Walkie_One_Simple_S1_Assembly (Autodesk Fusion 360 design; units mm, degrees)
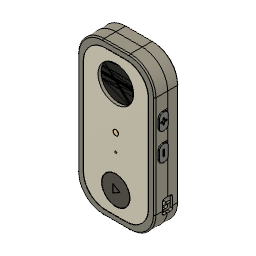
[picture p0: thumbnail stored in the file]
part number: 2026-09-16-19-14-38-361
part number: 2026-09-16-19-14-38-919
part number: 2026-09-16-19-14-39-016
part number: 2026-09-16-19-14-39-115
part number: 2026-09-16-19-14-39-169
part number: 2026-09-16-19-14-39-241
part number: 2026-09-16-19-14-39-296
part number: 2026-09-16-19-14-39-373
part number: 2026-09-16-19-14-39-442
part number: 2026-09-16-19-14-39-821
part number: 2026-09-16-19-14-39-875
part number: 2026-09-16-19-14-39-946
part number: 2026-09-16-19-14-39-999
part number: 2026-09-16-19-14-40-066
part number: 2026-09-16-19-14-40-133
part number: 2026-09-16-19-14-40-204
part number: 2026-09-16-19-14-40-267
part number: 2026-09-16-19-14-40-342
part number: 2026-09-16-19-06-38-531_1
part number: 2026-09-16-19-06-38-530_4
parameter "Overall_width_limit" = 78 comment "S1 design datum; rebuild source uses these stated values"
parameter "Case_width" = 76 comment "S1 design datum; rebuild source uses these stated values"
parameter "Case_height" = 150 comment "S1 design datum; rebuild source uses these stated values"
parameter "Case_depth" = 24 comment "S1 design datum; rebuild source uses these stated values"
parameter "Wall" = 2.4 comment "S1 design datum; rebuild source uses these stated values"
parameter "Front_skin" = 3 comment "S1 design datum; rebuild source uses these stated values"
parameter "Plan_corner" = 25 comment "S1 design datum; rebuild source uses these stated values"
parameter "Button_clearance_each_side" = 0.35 comment "S1 design datum; rebuild source uses these stated values"
base_feature "Base Feature1" bodies "03_Talk"
base_feature "Base Feature1" bodies "04_Volume_Up"
base_feature "Base Feature1" bodies "05_Volume_Down"
place_component sketch "Play symbol"
base_feature "Base Feature1" sketch "Play symbol" bodies "06_Play"
place_component sketch "45 degree reflector"
base_feature "Base Feature1" sketch "45 degree reflector" bodies "07_Control_Bridge"
base_feature "Base Feature1" bodies "08_Light_Guide_CLEAR"
base_feature "Base Feature1" bodies "01_Front_Shell"
base_feature "Base Feature1" bodies "02_Rear_Cover"
fillet "Fillet1" radius 1.2
fillet "Fillet1" radius 1.2
sketch "Play symbol" plane through (0, 0, 0) normal (0, 0, 1) x axis (1, 0, 0)
  line L1 (4, -47) -> (-3, -51)
  line L2 (-3, -43) -> (4, -47)
  line L3 (-3, -51) -> (-3, -43)
extrude "Extrude1" cut sketch "Play symbol" against normal blind 0.35 (magnitude of "-( 0.35 mm )")
work_plane "WorkPlane1" AlongDistance -2 ExtraOffset 0
sketch "45 degree reflector" plane through (0, -2, 0) normal (0, 1, 0) x axis (1, 0, 0)
  line L1 (3, 10) -> (-3, 10)
  line L2 (3, 4) -> (3, 10)
  line L3 (-3, 10) -> (3, 4)
extrude "Extrude1" cut sketch "45 degree reflector" distance 12
base_feature "Base Feature1" bodies "REF_03_Talk_switch_NOMINAL"
base_feature "Base Feature1" bodies "REF_04_Volume_Up_switch_NOMINAL"
base_feature "Base Feature1" bodies "REF_05_Volume_Down_switch_NOMINAL"
base_feature "Base Feature1" bodies "REF_Play_switch_12x12x4p3_NOMINAL"
base_feature "Base Feature1" bodies "REF_Battery_MAX_62x38p5x8p5"
base_feature "Base Feature1" bodies "REF_Antenna_96x21x0p2"
base_feature "Base Feature1" bodies "CHECK_J2_PHR_and_wire_turn"
base_feature "Base Feature1" bodies "CHECK_J10_PHR_and_wire_turn"
base_feature "Base Feature1" bodies "CHECK_J3_PHR_and_wire_turn"
base_feature "Base Feature1"
base_feature "Base Feature1"
base_feature "Base Feature1"
base_feature "Base Feature1"
base_feature "Base Feature1"
base_feature "Base Feature1"
base_feature "Base Feature1"
base_feature "Base Feature1"
base_feature "Base Feature1"
base_feature "Base Feature1"
base_feature "Base Feature1"
base_feature "Base Feature1"
base_feature "Base Feature1"
base_feature "Base Feature1"
base_feature "Base Feature1"
base_feature "Base Feature1"
base_feature "Base Feature1"
base_feature "Base Feature1"
base_feature "Base Feature1"
base_feature "Base Feature1"
base_feature "Base Feature1"
base_feature "Base Feature1"
base_feature "Base Feature1"
base_feature "Base Feature1"
base_feature "Base Feature1"
base_feature "Base Feature1"
base_feature "Base Feature1"
base_feature "Base Feature1"
base_feature "Base Feature1"
base_feature "Base Feature1"
base_feature "Base Feature1"
base_feature "Base Feature1"
base_feature "Base Feature1"
base_feature "Base Feature1"
base_feature "Base Feature1"
base_feature "Base Feature1"
base_feature "Base Feature1"
base_feature "Base Feature1"
base_feature "Base Feature1"
base_feature "Base Feature1"
base_feature "Base Feature1"
base_feature "Base Feature1"
base_feature "Base Feature1"
base_feature "Base Feature1"
base_feature "Base Feature1"
base_feature "Base Feature1"
base_feature "Base Feature1"
base_feature "Base Feature1"
base_feature "Base Feature1"
base_feature "Base Feature1"
base_feature "Base Feature1"
base_feature "Base Feature1"
base_feature "Base Feature1"
base_feature "Base Feature1"
base_feature "Base Feature1"
base_feature "Base Feature1"
base_feature "Base Feature1"
base_feature "Base Feature1"
base_feature "Base Feature1"
base_feature "Base Feature1"
base_feature "Base Feature1"
base_feature "Base Feature1"
base_feature "Base Feature1"
base_feature "Base Feature1"
base_feature "Base Feature1"
base_feature "Base Feature1"
base_feature "Base Feature1"
base_feature "Base Feature1"
base_feature "Base Feature1"
base_feature "Base Feature1"
base_feature "Base Feature1"
base_feature "Base Feature1"
base_feature "Base Feature1"
base_feature "Base Feature1"
base_feature "Base Feature1"
base_feature "Base Feature1"
base_feature "Base Feature1"
base_feature "Base Feature1"
base_feature "Base Feature1"
base_feature "Base Feature1"
base_feature "Base Feature1"
base_feature "Base Feature1"
base_feature "Base Feature1"
base_feature "Base Feature1"
base_feature "Base Feature1"
base_feature "Base Feature1"
base_feature "Base Feature1"
base_feature "Base Feature1"
base_feature "Base Feature1"
base_feature "Base Feature1"
base_feature "Base Feature1"
base_feature "Base Feature1"
base_feature "Base Feature1"
base_feature "Base Feature1"
base_feature "Base Feature1"
base_feature "Base Feature1"
base_feature "Base Feature1"
base_feature "Base Feature1"
base_feature "Base Feature1"
base_feature "Base Feature1"
base_feature "Base Feature1"
base_feature "Base Feature1"
base_feature "Base Feature1"
base_feature "Base Feature1"
base_feature "Base Feature1"
base_feature "Base Feature1"
base_feature "Base Feature1"
base_feature "Base Feature1"
base_feature "Base Feature1"
base_feature "Base Feature1"
base_feature "Base Feature1"
base_feature "Base Feature1"
base_feature "Base Feature1"
base_feature "Base Feature1"
base_feature "Base Feature1"
base_feature "Base Feature1"
base_feature "Base Feature1"
base_feature "Base Feature1"
base_feature "Base Feature1"
base_feature "Base Feature1"
base_feature "Base Feature1"
base_feature "Base Feature1"
base_feature "Base Feature1"
base_feature "Base Feature1"
base_feature "Base Feature1"
base_feature "Base Feature1"
base_feature "Base Feature1"
base_feature "Base Feature1"
base_feature "Base Feature1"
base_feature "Base Feature1"
base_feature "Base Feature1"
base_feature "Base Feature1"
base_feature "Base Feature1"
base_feature "Base Feature1"
base_feature "Base Feature1"
base_feature "Base Feature1"
base_feature "Base Feature1"
base_feature "Base Feature1"
base_feature "Base Feature1"
base_feature "Base Feature1"
base_feature "Base Feature1"
base_feature "Base Feature1"
base_feature "Base Feature1"
base_feature "Base Feature1"
base_feature "Base Feature1"
base_feature "Base Feature1"
base_feature "Base Feature1"
base_feature "Base Feature1"
base_feature "Base Feature1"
base_feature "Base Feature1"
base_feature "Base Feature1"
base_feature "Base Feature1"
base_feature "Base Feature1"
base_feature "Base Feature1"
base_feature "Base Feature1"
base_feature "Base Feature1"
base_feature "Base Feature1"
base_feature "Base Feature1"
base_feature "Base Feature1"
base_feature "Base Feature1"
base_feature "Base Feature1"
base_feature "Base Feature1"
base_feature "Base Feature1"
base_feature "Base Feature1"
base_feature "Base Feature1"
base_feature "Base Feature1"
base_feature "Base Feature1"
base_feature "Base Feature1"
base_feature "Base Feature1"
base_feature "Base Feature1"
base_feature "Base Feature1"
base_feature "Base Feature1"
base_feature "Base Feature1"
base_feature "Base Feature1"
base_feature "Base Feature1"
base_feature "Base Feature1"
base_feature "Base Feature1"
base_feature "Base Feature1"
base_feature "Base Feature1"
base_feature "Base Feature1"
base_feature "Base Feature1"
base_feature "Base Feature1"
base_feature "Base Feature1"
base_feature "Base Feature1"
base_feature "Base Feature1"
base_feature "Base Feature1"
base_feature "Base Feature1"
base_feature "Base Feature1"
base_feature "Base Feature1"
base_feature "Base Feature1"
base_feature "Base Feature1"
base_feature "Base Feature1"
base_feature "Base Feature1"
base_feature "Base Feature1"
base_feature "Base Feature1"
base_feature "Base Feature1"
base_feature "Base Feature1"
base_feature "Base Feature1"
base_feature "Base Feature1"
base_feature "Base Feature1"
base_feature "Base Feature1"
base_feature "Base Feature1"
base_feature "Base Feature1"
base_feature "Base Feature1"
base_feature "Base Feature1"
base_feature "Base Feature1"
base_feature "Base Feature1"
base_feature "Base Feature1"
base_feature "Base Feature1"
base_feature "Base Feature1"
base_feature "Base Feature1"
base_feature "Base Feature1"
base_feature "Base Feature1"
base_feature "Base Feature1"
base_feature "Base Feature1"
base_feature "Base Feature1"
base_feature "Base Feature1"
base_feature "Base Feature1"
base_feature "Base Feature1"
base_feature "Base Feature1"
base_feature "Base Feature1"
base_feature "Base Feature1"
base_feature "Base Feature1"
base_feature "Base Feature1"
base_feature "Base Feature1"
base_feature "Base Feature1"
base_feature "Base Feature1"
base_feature "Base Feature1"
base_feature "Base Feature1"
base_feature "Base Feature1"
base_feature "Base Feature1"
base_feature "Base Feature1"
base_feature "Base Feature1"
base_feature "Base Feature1"
base_feature "Base Feature1"
base_feature "Base Feature1"
base_feature "Base Feature1"
base_feature "Base Feature1"
base_feature "Base Feature1"
base_feature "Base Feature1"
base_feature "Base Feature1"
base_feature "Base Feature1"
base_feature "Base Feature1"
base_feature "Base Feature1"
base_feature "Base Feature1"
base_feature "Base Feature1"
base_feature "Base Feature1"
base_feature "Base Feature1"
base_feature "Base Feature1"
base_feature "Base Feature1"
base_feature "Base Feature1"
base_feature "Base Feature1"
base_feature "Base Feature1"
base_feature "Base Feature1"
base_feature "Base Feature1"
base_feature "Base Feature1"
base_feature "Base Feature1"
base_feature "Base Feature1"
base_feature "Base Feature1"
base_feature "Base Feature1"
base_feature "Base Feature1"
base_feature "Base Feature1"
base_feature "Base Feature1"
base_feature "Base Feature1"
base_feature "Base Feature1"
base_feature "Base Feature1"
base_feature "Base Feature1"
base_feature "Base Feature1"
base_feature "Base Feature1"
base_feature "Base Feature1"
base_feature "Base Feature1"
base_feature "Base Feature1"
base_feature "Base Feature1"
base_feature "Base Feature1"
base_feature "Base Feature1"
base_feature "Base Feature1"
base_feature "Base Feature1"
base_feature "Base Feature1"
base_feature "Base Feature1"
base_feature "Base Feature1"
base_feature "Base Feature1"
base_feature "Base Feature1"
base_feature "Base Feature1"
base_feature "Base Feature1"
base_feature "Base Feature1"
base_feature "Base Feature1"
base_feature "Base Feature1"
base_feature "Base Feature1"
base_feature "Base Feature1"
base_feature "Base Feature1"
base_feature "Base Feature1"
base_feature "Base Feature1"
base_feature "Base Feature1"
base_feature "Base Feature1"
base_feature "Base Feature1"
base_feature "Base Feature1"
base_feature "Base Feature1"
base_feature "Base Feature1"
base_feature "Base Feature1"
base_feature "Base Feature1"
base_feature "Base Feature1"
base_feature "Base Feature1"
base_feature "Base Feature1"
base_feature "Base Feature1"
base_feature "Base Feature1"
base_feature "Base Feature1"
base_feature "Base Feature1"
base_feature "Base Feature1"
base_feature "Base Feature1"
base_feature "Base Feature1"
base_feature "Base Feature1"
base_feature "Base Feature1"
base_feature "Base Feature1"
base_feature "Base Feature1"
base_feature "Base Feature1"
base_feature "Base Feature1"
base_feature "Base Feature1"
base_feature "Base Feature1"
base_feature "Base Feature1"
base_feature "Base Feature1"
base_feature "Base Feature1"
base_feature "Base Feature1"
base_feature "Base Feature1"
base_feature "Base Feature1"
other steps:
extrude "Extrude1" cut sketch "45 degree reflector" distance 12
create_component "CreateComponent1"
create_component "CreateComponent2"
create_component "CreateComponent3"
create_component "CreateComponent4" sketch "Play symbol"
create_component "CreateComponent5" sketch "45 degree reflector"
create_component "CreateComponent6"
create_component "CreateComponent7"
create_component "CreateComponent8"
create_component "CreateComponent9"
create_component "CreateComponent10"
create_component "CreateComponent11"
create_component "CreateComponent12"
create_component "CreateComponent13"
create_component "CreateComponent14"
create_component "CreateComponent15"
create_component "CreateComponent16"
create_component "CreateComponent17"
create_component "CreateComponent18"
create_component "CreateComponent1"
create_component "CreateComponent2"
create_component "CreateComponent3"
create_component "CreateComponent4"
create_component "CreateComponent5"
create_component "CreateComponent6"
create_component "CreateComponent7"
create_component "CreateComponent8"
create_component "CreateComponent9"
create_component "CreateComponent10"
create_component "CreateComponent11"
create_component "CreateComponent12"
create_component "CreateComponent13"
create_component "CreateComponent14"
create_component "CreateComponent15"
create_component "CreateComponent16"
create_component "CreateComponent17"
create_component "CreateComponent18"
create_component "CreateComponent19"
create_component "CreateComponent20"
create_component "CreateComponent21"
create_component "CreateComponent22"
create_component "CreateComponent23"
create_component "CreateComponent24"
create_component "CreateComponent25"
create_component "CreateComponent26"
create_component "CreateComponent27"
create_component "CreateComponent28"
create_component "CreateComponent29"
create_component "CreateComponent30"
create_component "CreateComponent31"
create_component "CreateComponent32"
create_component "CreateComponent33"
create_component "CreateComponent34"
create_component "CreateComponent35"
create_component "CreateComponent36"
create_component "CreateComponent37"
create_component "CreateComponent38"
create_component "CreateComponent39"
create_component "CreateComponent40"
create_component "CreateComponent41"
create_component "CreateComponent42"
create_component "CreateComponent43"
create_component "CreateComponent44"
create_component "CreateComponent45"
create_component "CreateComponent46"
create_component "CreateComponent47"
create_component "CreateComponent48"
create_component "CreateComponent49"
create_component "CreateComponent50"
create_component "CreateComponent51"
create_component "CreateComponent52"
create_component "CreateComponent53"
create_component "CreateComponent54"
create_component "CreateComponent55"
create_component "CreateComponent56"
create_component "CreateComponent57"
create_component "CreateComponent58"
create_component "CreateComponent59"
create_component "CreateComponent60"
create_component "CreateComponent61"
create_component "CreateComponent62"
create_component "CreateComponent63"
create_component "CreateComponent64"
create_component "CreateComponent65"
create_component "CreateComponent66"
create_component "CreateComponent67"
create_component "CreateComponent68"
create_component "CreateComponent69"
create_component "CreateComponent70"
create_component "CreateComponent71"
create_component "CreateComponent72"
create_component "CreateComponent73"
create_component "CreateComponent74"
create_component "CreateComponent75"
create_component "CreateComponent76"
create_component "CreateComponent77"
create_component "CreateComponent78"
create_component "CreateComponent79"
create_component "CreateComponent80"
create_component "CreateComponent81"
create_component "CreateComponent82"
create_component "CreateComponent83"
create_component "CreateComponent84"
create_component "CreateComponent85"
create_component "CreateComponent86"
create_component "CreateComponent87"
create_component "CreateComponent88"
create_component "CreateComponent89"
create_component "CreateComponent90"
create_component "CreateComponent91"
create_component "CreateComponent92"
create_component "CreateComponent93"
create_component "CreateComponent94"
create_component "CreateComponent95"
create_component "CreateComponent96"
create_component "CreateComponent97"
create_component "CreateComponent98"
create_component "CreateComponent99"
create_component "CreateComponent100"
create_component "CreateComponent101"
create_component "CreateComponent102"
create_component "CreateComponent103"
create_component "CreateComponent104"
create_component "CreateComponent105"
create_component "CreateComponent106"
create_component "CreateComponent107"
create_component "CreateComponent108"
create_component "CreateComponent109"
create_component "CreateComponent110"
create_component "CreateComponent111"
create_component "CreateComponent112"
create_component "CreateComponent113"
create_component "CreateComponent114"
create_component "CreateComponent115"
create_component "CreateComponent116"
create_component "CreateComponent117"
create_component "CreateComponent118"
create_component "CreateComponent119"
create_component "CreateComponent120"
create_component "CreateComponent121"
create_component "CreateComponent122"
create_component "CreateComponent123"
create_component "CreateComponent124"
create_component "CreateComponent125"
create_component "CreateComponent126"
create_component "CreateComponent127"
create_component "CreateComponent128"
create_component "CreateComponent129"
create_component "CreateComponent130"
create_component "CreateComponent131"
create_component "CreateComponent132"
create_component "CreateComponent133"
create_component "CreateComponent134"
create_component "CreateComponent135"
create_component "CreateComponent136"
create_component "CreateComponent137"
create_component "CreateComponent138"
create_component "CreateComponent139"
create_component "CreateComponent140"
create_component "CreateComponent141"
create_component "CreateComponent142"
create_component "CreateComponent143"
create_component "CreateComponent144"
create_component "CreateComponent145"
create_component "CreateComponent146"
create_component "CreateComponent147"
create_component "CreateComponent148"
create_component "CreateComponent149"
create_component "CreateComponent150"
create_component "CreateComponent151"
create_component "CreateComponent152"
create_component "CreateComponent153"
create_component "CreateComponent154"
create_component "CreateComponent155"
create_component "CreateComponent156"
create_component "CreateComponent157"
create_component "CreateComponent158"
create_component "CreateComponent159"
create_component "CreateComponent160"
create_component "CreateComponent161"
create_component "CreateComponent162"
create_component "CreateComponent163"
create_component "CreateComponent164"
create_component "CreateComponent165"
create_component "CreateComponent166"
create_component "CreateComponent167"
create_component "CreateComponent168"
create_component "CreateComponent169"
create_component "CreateComponent170"
create_component "CreateComponent171"
create_component "CreateComponent172"
create_component "CreateComponent173"
create_component "CreateComponent174"
create_component "CreateComponent175"
create_component "CreateComponent176"
create_component "CreateComponent177"
create_component "CreateComponent178"
create_component "CreateComponent179"
create_component "CreateComponent180"
create_component "CreateComponent181"
create_component "CreateComponent182"
create_component "CreateComponent183"
create_component "CreateComponent184"
create_component "CreateComponent185"
create_component "CreateComponent186"
create_component "CreateComponent187"
create_component "CreateComponent188"
create_component "CreateComponent189"
create_component "CreateComponent190"
create_component "CreateComponent191"
create_component "CreateComponent192"
create_component "CreateComponent193"
create_component "CreateComponent194"
create_component "CreateComponent195"
create_component "CreateComponent196"
create_component "CreateComponent197"
create_component "CreateComponent198"
create_component "CreateComponent199"
create_component "CreateComponent200"
create_component "CreateComponent201"
create_component "CreateComponent202"
create_component "CreateComponent203"
create_component "CreateComponent204"
create_component "CreateComponent205"
create_component "CreateComponent206"
create_component "CreateComponent207"
create_component "CreateComponent208"
create_component "CreateComponent209"
create_component "CreateComponent210"
create_component "CreateComponent211"
create_component "CreateComponent212"
create_component "CreateComponent213"
create_component "CreateComponent214"
create_component "CreateComponent215"
create_component "CreateComponent216"
create_component "CreateComponent217"
create_component "CreateComponent218"
create_component "CreateComponent219"
create_component "CreateComponent220"
create_component "CreateComponent221"
create_component "CreateComponent222"
create_component "CreateComponent223"
create_component "CreateComponent224"
create_component "CreateComponent225"
create_component "CreateComponent226"
create_component "CreateComponent227"
create_component "CreateComponent228"
create_component "CreateComponent229"
create_component "CreateComponent230"
create_component "CreateComponent231"
create_component "CreateComponent232"
create_component "CreateComponent233"
create_component "CreateComponent234"
create_component "CreateComponent235"
create_component "CreateComponent236"
create_component "CreateComponent237"
create_component "CreateComponent238"
create_component "CreateComponent239"
create_component "CreateComponent240"
create_component "CreateComponent241"
create_component "CreateComponent242"
create_component "CreateComponent243"
create_component "CreateComponent244"
create_component "CreateComponent245"
create_component "CreateComponent246"
create_component "CreateComponent247"
create_component "CreateComponent248"
create_component "CreateComponent249"
create_component "CreateComponent250"
create_component "CreateComponent251"
create_component "CreateComponent252"
create_component "CreateComponent253"
create_component "CreateComponent254"
create_component "CreateComponent255"
create_component "CreateComponent256"
create_component "CreateComponent257"
create_component "CreateComponent258"
create_component "CreateComponent259"
create_component "CreateComponent260"
create_component "CreateComponent261"
create_component "CreateComponent262"
create_component "CreateComponent263"
create_component "CreateComponent264"
create_component "CreateComponent265"
create_component "CreateComponent266"
create_component "CreateComponent267"
create_component "CreateComponent268"
create_component "CreateComponent269"
create_component "CreateComponent270"
create_component "CreateComponent271"
create_component "CreateComponent272"
create_component "CreateComponent273"
create_component "CreateComponent274"
create_component "CreateComponent275"
create_component "CreateComponent276"
create_component "CreateComponent277"
create_component "CreateComponent278"
create_component "CreateComponent279"
create_component "CreateComponent280"
create_component "CreateComponent281"
create_component "CreateComponent282"
create_component "CreateComponent283"
create_component "CreateComponent284"
create_component "CreateComponent285"
create_component "CreateComponent286"
create_component "CreateComponent287"
create_component "CreateComponent288"
create_component "CreateComponent289"
create_component "CreateComponent290"
create_component "CreateComponent291"
create_component "CreateComponent292"
create_component "CreateComponent293"
create_component "CreateComponent294"
create_component "CreateComponent295"
create_component "CreateComponent296"
create_component "CreateComponent297"
create_component "CreateComponent298"
create_component "CreateComponent299"
create_component "CreateComponent300"
create_component "CreateComponent301"
create_component "CreateComponent302"
create_component "CreateComponent303"
create_component "CreateComponent304"
create_component "CreateComponent305"
create_component "CreateComponent306"
create_component "CreateComponent19"
create_component "CreateComponent20"
create_component "CreateComponent1"
create_component "CreateComponent2"
create_component "CreateComponent3"
create_component "CreateComponent4"
create_component "CreateComponent21"
create_component "CreateComponent1"
create_component "CreateComponent2"
create_component "CreateComponent3"
create_component "CreateComponent4"
create_component "CreateComponent5"
create_component "CreateComponent6"
create_component "CreateComponent22"
create_component "CreateComponent1"
create_component "CreateComponent2"
create_component "CreateComponent3"
create_component "CreateComponent4"
create_component "CreateComponent5"
create_component "CreateComponent6"
create_component "CreateComponent7"
named bodies: "03_Talk", "04_Volume_Up", "05_Volume_Down", "06_Play", "07_Control_Bridge", "08_Light_Guide_CLEAR", "01_Front_Shell", "02_Rear_Cover", "REF_03_Talk_switch_NOMINAL", "REF_04_Volume_Up_switch_NOMINAL", "REF_05_Volume_Down_switch_NOMINAL", "REF_Play_switch_12x12x4p3_NOMINAL", "REF_Battery_MAX_62x38p5x8p5", "REF_Antenna_96x21x0p2", "CHECK_J2_PHR_and_wire_turn", "CHECK_J10_PHR_and_wire_turn", "CHECK_J3_PHR_and_wire_turn"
